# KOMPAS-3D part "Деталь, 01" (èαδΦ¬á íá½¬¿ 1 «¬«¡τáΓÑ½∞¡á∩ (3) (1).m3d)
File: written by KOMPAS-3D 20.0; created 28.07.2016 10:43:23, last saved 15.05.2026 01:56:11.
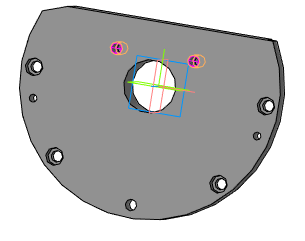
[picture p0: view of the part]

Document properties: Полное имя файла: E:\test_kompas\all_v18\Крышка балки 1 окончательная (3) (1).m3d

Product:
- Part/product: Деталь  | designation 01
    Масса: 9.68884
  - Body: Тело 1
- Part/product: Деталь
    Масса: 9.68884
  - Body: Тело 1

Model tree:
1. Эскиз:1
2. Операция выдавливания:1
     Расстояние 1 = 40
3. Эскиз:2  (with: Операция выдавливания:1)
4. Элемент выдавливания:2
     Расстояние 2 = 20
5. Эскиз:13  (with: Операция выдавливания:1)
6. Элемент выдавливания:5
     Расстояние 2 = 40
7. Эскиз:14  (with: Операция выдавливания:1)
8. Эскиз:15  (with: Операция выдавливания:1, Элемент выдавливания:2)
9. Элемент выдавливания:6
     Расстояние 2 = 40
10. Эскиз:16  (with: Операция выдавливания:1, Элемент выдавливания:2)
11. Элемент выдавливания:7
     Расстояние 2 = 11
12. Отверстие:3  (with: Операция выдавливания:1)  (labels: M12)
     Глубина выреза = 30; Диаметр отверстия = 10.1056; Угол конуса дна = 118; Расстояние 1 = 31; Расстояние 2 = 46.4075
13. M12  (with: Отверстие:3, Операция выдавливания:1)  (labels: M12; cil0_24705-2004 coarse)
     Длина резьбы = 25; Шаг резьбы = 1.75; Номинальный диаметр резьбы = 12
14. Отверстие:4  (with: Операция выдавливания:1, M12)  (labels: M12; cil0_24705-2004 coarse)
     Глубина выреза = 30; Диаметр отверстия = 10.1056; Угол конуса дна = 118; Расстояние 1 = 31; Расстояние 2 = 70.8326; Длина резьбы = 25; Шаг резьбы = 1.75; Номинальный диаметр резьбы = 12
